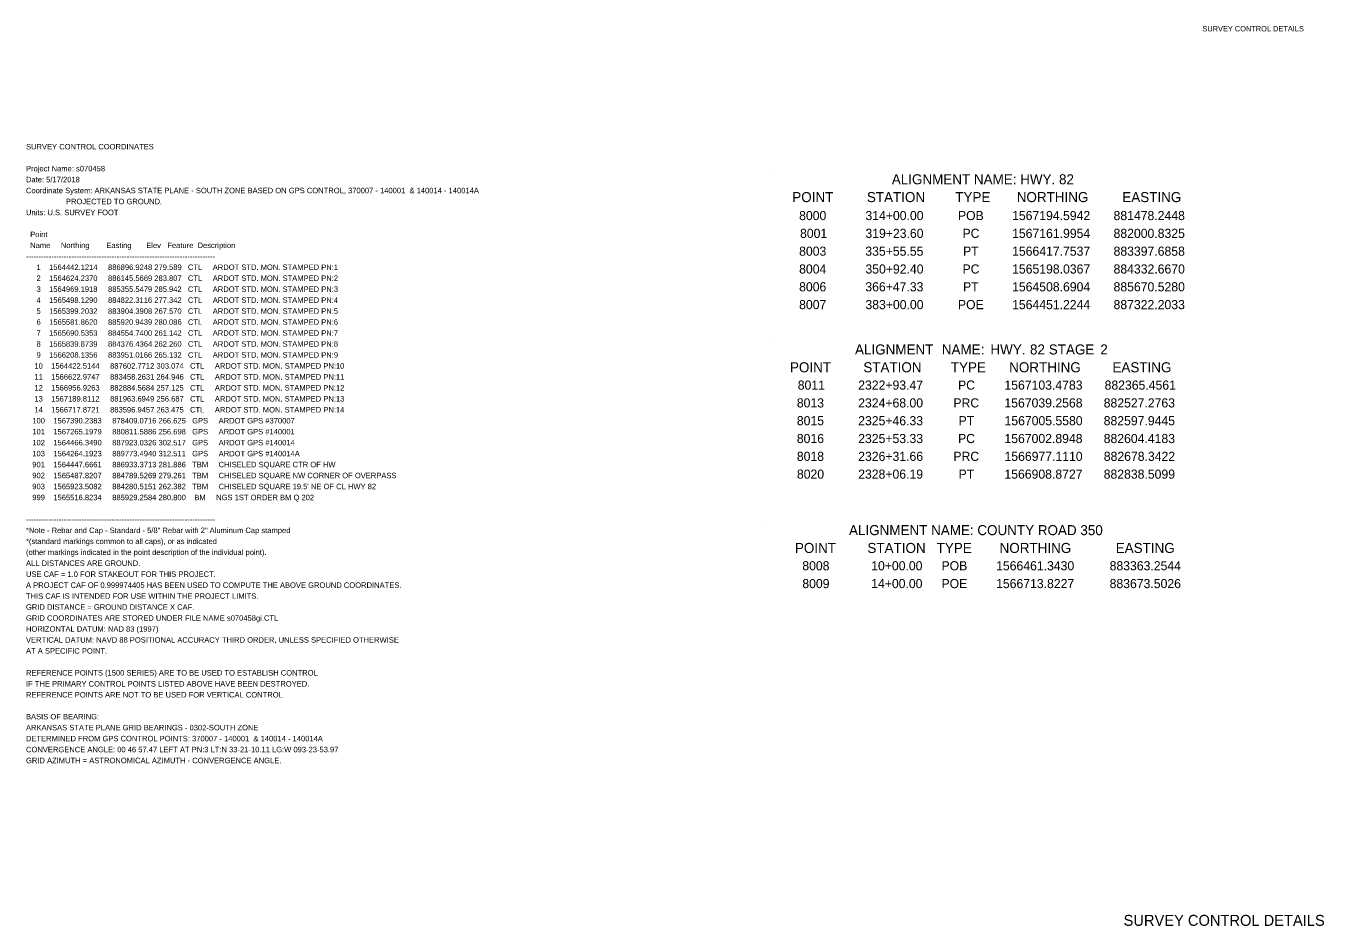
# Model space of a CAD drawing. Extents: x 878822 to 880243, y 1568127 to 1569112.
import ezdxf

# ---------------------------------------------------------------- set-up
doc = ezdxf.new("R2010")
doc.units = 0
for name, color, linetype in [('Default', 7, 'Continuous'), ('R_Border', 7, 'Continuous'), ('R_Border Prem', 7, 'Continuous')]:
    doc.layers.add(name, color=color, linetype=linetype)

msp = doc.modelspace()

# ---------------------------------------------------------------- linework, layer by layer
at = {"layer": 'R_Border Prem'}
for p, q in [((879640.9, 1568956), (879640.9, 1568956)), ((879642.8, 1568767.6), (879642.8, 1568767.6)), ((879629.3, 1568569.8), (879629.3, 1568569.8))]:
    msp.add_line(p, q, dxfattribs=at)

# ---------------------------------------------------------------- texts
at = {"layer": 'Default'}
for s, height, p in [('SURVEY CONTROL COORDINATES ', 6, (878822, 1568976.9)), ('Project Name: s070458 ', 6, (878822, 1568952.9)), ('Date: 5/17/2018 ', 6, (878822, 1568940.9)), ('ALIGNMENT NAME: HWY. 82', 11, (879770.1, 1568938.7)), ('Coordinate System: ARKANSAS STATE PLANE - SOUTH ZONE BASED ON GPS CONTROL, 370007 - 140001  & 140014 - 140014A', 6, (878822, 1568928.9)), ('                   PROJECTED TO GROUND. ', 6, (878822, 1568916.9)), ('POINT', 11, (879661.1, 1568919.2)), ('STATION', 11, (879742.8, 1568919.2)), ('TYPE', 11, (879839.6, 1568919.2)), ('NORTHING', 11, (879906.9, 1568919.2)), ('EASTING', 11, (880022.5, 1568919.2)), ('Units: U.S. SURVEY FOOT ', 6, (878822, 1568904.9)), ('8000', 10, (879668.6, 1568899.5)), ('314+00.00', 10, (879741.2, 1568899.5)), ('POB', 10, (879842.5, 1568899.5)), ('1567194.5942', 10, (879901.8, 1568899.5)), ('881478.2448', 10, (880012.9, 1568899.5)), ('  Point ', 6, (878822, 1568880.9)), ('8001', 10, (879669.6, 1568880)), ('319+23.60', 10, (879741.2, 1568880)), ('PC', 10, (879847.5, 1568880)), ('1567161.9954', 10, (879901.8, 1568880)), ('882000.8325', 10, (880012.9, 1568880)), ('  Name     Northing        Easting       Elev   Feature  Description ', 6, (878822, 1568868.9)), ('8003', 10, (879668.6, 1568860.5)), ('335+55.55', 10, (879741.1, 1568860.5)), ('PT', 10, (879848.1, 1568860.5)), ('1566417.7537', 10, (879901.8, 1568860.5)), ('883397.6858', 10, (880012.9, 1568860.5)), ('--------------------------------------------------------------------------- ', 6, (878822, 1568856.9)), ('8004', 10, (879668.6, 1568841)), ('350+92.40', 10, (879741.2, 1568841)), ('PC', 10, (879847.5, 1568841)), ('1565198.0367', 10, (879901.8, 1568841)), ('884332.6670', 10, (880012.9, 1568841)), ('     2    1564624.2370     886145.5669 283.807   CTL     ARDOT STD. MON. STAMPED PN:2 ', 6, (878822, 1568832.9)), ('     1    1564442.1214     886896.9248 279.589   CTL     ARDOT STD. MON. STAMPED PN:1 ', 6, (878822, 1568844.9)), ('     3    1564969.1918     885355.5479 285.942   CTL     ARDOT STD. MON. STAMPED PN:3 ', 6, (878822, 1568820.9)), ('8006', 10, (879668.6, 1568821.5)), ('366+47.33', 10, (879741.1, 1568821.5)), ('PT', 10, (879848.1, 1568821.5)), ('1564508.6904', 10, (879901.8, 1568821.5)), ('885670.5280', 10, (880012.9, 1568821.5)), ('     4    1565498.1290     884822.3116 277.342   CTL     ARDOT STD. MON. STAMPED PN:4 ', 6, (878822, 1568808.9)), ('8007', 10, (879668.6, 1568802)), ('383+00.00', 10, (879741.2, 1568802)), ('POE', 10, (879842.5, 1568802)), ('1564451.2244', 10, (879901.8, 1568802)), ('887322.2033', 10, (880012.9, 1568802)), ('     5    1565399.2032     883904.3908 267.570   CTL     ARDOT STD. MON. STAMPED PN:5 ', 6, (878822, 1568796.9)), ('     6    1565581.8620     885920.9439 280.086   CTL     ARDOT STD. MON. STAMPED PN:6 ', 6, (878822, 1568784.9)), ('     7    1565690.5353     884554.7400 261.142   CTL     ARDOT STD. MON. STAMPED PN:7 ', 6, (878822, 1568772.9)), ('     8    1565839.8739     884376.4364 262.260   CTL     ARDOT STD. MON. STAMPED PN:8 ', 6, (878822, 1568760.9)), ('     9    1566208.1356     883951.0166 265.132   CTL     ARDOT STD. MON. STAMPED PN:9 ', 6, (878822, 1568748.9)), ('ALIGNMENT', 11, (879729.8, 1568752.4)), (' NAME:', 11, (879820.8, 1568752.4)), (' HWY.', 11, (879874, 1568752.4)), (' 82', 11, (879917.3, 1568752.4)), (' STAGE', 11, (879937.9, 1568752.4)), (' 2', 11, (879994.3, 1568752.4)), ('    10    1564422.5144     887602.7712 303.074   CTL     ARDOT STD. MON. STAMPED PN:10 ', 6, (878822, 1568736.9)), ('POINT', 11, (879658.6, 1568732.9)), ('STATION', 11, (879738.9, 1568732.9)), ('TYPE', 11, (879834.7, 1568732.9)), ('NORTHING', 11, (879898.6, 1568732.9)), ('EASTING', 11, (880011.7, 1568732.9)), ('    11    1566622.9747     883458.2631 264.946   CTL     ARDOT STD. MON. STAMPED PN:11 ', 6, (878822, 1568724.9)), ('8011', 10, (879667.1, 1568713.9)), ('2322+93.47', 10, (879733.3, 1568713.9)), ('PC', 10, (879842.6, 1568713.9)), ('1567103.4783', 10, (879893.4, 1568713.9)), ('882365.4561', 10, (880003.1, 1568713.9)), ('    12    1566956.9263     882884.5684 257.125   CTL     ARDOT STD. MON. STAMPED PN:12 ', 6, (878822, 1568712.9)), ('    13    1567189.8112     881963.6949 256.687   CTL     ARDOT STD. MON. STAMPED PN:13 ', 6, (878822, 1568700.9)), ('    14    1566717.8721     883596.9457 263.475   CTL     ARDOT STD. MON. STAMPED PN:14 ', 6, (878822, 1568688.9)), ('8013', 10, (879666.1, 1568694.4)), ('2324+68.00', 10, (879733.3, 1568694.4)), ('PRC', 10, (879837.5, 1568694.4)), ('1567039.2568', 10, (879893.4, 1568694.4)), ('882527.2763', 10, (880002.1, 1568694.4)), ('   100    1567390.2383     878409.0716 266.625   GPS     ARDOT GPS #370007 ', 6, (878822, 1568676.9)), ('8015', 10, (879666.1, 1568674.9)), ('2325+46.33', 10, (879733.3, 1568674.9)), ('PT', 10, (879843.2, 1568674.9)), ('1567005.5580', 10, (879893.5, 1568674.9)), ('882597.9445', 10, (880002.1, 1568674.9)), ('   101    1567265.1979     880811.5886 256.698   GPS     ARDOT GPS #140001 ', 6, (878822, 1568664.9)), ('   102    1564466.3490     887923.0326 302.517   GPS     ARDOT GPS #140014 ', 6, (878822, 1568652.9)), ('8016', 10, (879666.1, 1568655.4)), ('2325+53.33', 10, (879733.3, 1568655.4)), ('PC', 10, (879842.6, 1568655.4)), ('1567002.8948', 10, (879893.4, 1568655.4)), ('882604.4183', 10, (880002.1, 1568655.4)), ('   103    1564264.1923     889773.4940 312.511   GPS     ARDOT GPS #140014A ', 6, (878822, 1568640.9)), ('8018', 10, (879666.1, 1568635.9)), ('2326+31.66', 10, (879733.3, 1568635.9)), ('PRC', 10, (879837.5, 1568635.9)), ('1566977.1110', 10, (879893.5, 1568635.9)), ('882678.3422', 10, (880002.2, 1568635.9)), ('   901    1564447.6661     886933.3713 281.886   TBM     CHISELED SQUARE CTR OF HW', 6, (878822, 1568628.9)), ('8020', 10, (879666.2, 1568616.4)), ('2328+06.19', 10, (879733.3, 1568616.4)), ('PT', 10, (879843.2, 1568616.4)), ('1566908.8727', 10, (879893.4, 1568616.4)), ('882838.5099', 10, (880002.1, 1568616.4)), ('   902    1565487.8207     884789.5269 279.261   TBM     CHISELED SQUARE NW CORNER OF OVERPASS ', 6, (878822, 1568616.9)), ("   903    1565923.5082     884280.5151 262.382   TBM     CHISELED SQUARE 19.5' NE OF CL HWY 82 ", 6, (878822, 1568604.9)), ('   999    1565516.8234     885929.2584 280.800    BM     NGS 1ST ORDER BM Q 202 ', 6, (878822, 1568592.9)), ('--------------------------------------------------------------------------- ', 6, (878822, 1568568.9)), ('*Note - Rebar and Cap - Standard - 5/8" Rebar with 2" Aluminum Cap stamped ', 6, (878822, 1568556.9)), ('ALIGNMENT NAME: COUNTY ROAD 350', 11, (879723.2, 1568554.6)), ('*(standard markings common to all caps), or as indicated ', 6, (878822, 1568544.9)), ('(other markings indicated in the point description of the individual point).  ', 6, (878822, 1568532.9)), ('POINT', 11, (879664, 1568535.1)), ('STATION', 11, (879743.4, 1568535.1)), ('TYPE', 11, (879819.2, 1568535.1)), ('NORTHING', 11, (879888.1, 1568535.1)), ('EASTING', 11, (880015.3, 1568535.1)), ('ALL DISTANCES ARE GROUND. ', 6, (878822, 1568520.9)), ('8008', 10, (879672.1, 1568516.1)), ('10+00.00', 10, (879747.5, 1568516.1)), ('POB', 10, (879824.5, 1568516.1)), ('1566461.3430', 10, (879884.3, 1568516.1)), ('883363.2544', 10, (880008.6, 1568516.1)), ('USE CAF = 1.0 FOR STAKEOUT FOR THIS PROJECT. ', 6, (878822, 1568508.9)), ('A PROJECT CAF OF 0.999974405 HAS BEEN USED TO COMPUTE THE ABOVE GROUND COORDINATES. ', 6, (878822, 1568496.9)), ('8009', 10, (879672.1, 1568496.6)), ('14+00.00', 10, (879747.5, 1568496.6)), ('POE', 10, (879824.5, 1568496.6)), ('1566713.8227', 10, (879884.3, 1568496.6)), ('883673.5026', 10, (880008.6, 1568496.6)), ('THIS CAF IS INTENDED FOR USE WITHIN THE PROJECT LIMITS. ', 6, (878822, 1568484.9)), ('GRID DISTANCE = GROUND DISTANCE X CAF. ', 6, (878822, 1568472.9)), ('GRID COORDINATES ARE STORED UNDER FILE NAME s070458gi.CTL  ', 6, (878822, 1568460.9)), ('HORIZONTAL DATUM: NAD 83 (1997) ', 6, (878822, 1568448.9)), ('VERTICAL DATUM: NAVD 88 POSITIONAL ACCURACY THIRD ORDER, UNLESS SPECIFIED OTHERWISE  ', 6, (878822, 1568436.9)), ('AT A SPECIFIC POINT. ', 6, (878822, 1568424.9)), ('REFERENCE POINTS (1500 SERIES) ARE TO BE USED TO ESTABLISH CONTROL ', 6, (878822, 1568400.9)), ('REFERENCE POINTS ARE NOT TO BE USED FOR VERTICAL CONTROL ', 6, (878822, 1568376.9)), ('IF THE PRIMARY CONTROL POINTS LISTED ABOVE HAVE BEEN DESTROYED. ', 6, (878822, 1568388.9)), ('BASIS OF BEARING: ', 6, (878822, 1568352.9)), ('ARKANSAS STATE PLANE GRID BEARINGS - 0302-SOUTH ZONE ', 6, (878822, 1568340.9)), ('DETERMINED FROM GPS CONTROL POINTS: 370007 - 140001  & 140014 - 140014A', 6, (878822, 1568328.9)), ('CONVERGENCE ANGLE: 00 46 57.47 LEFT AT PN:3 LT:N 33-21-10.11 LG:W 093-23-53.97', 6, (878822, 1568316.9)), ('GRID AZIMUTH = ASTRONOMICAL AZIMUTH - CONVERGENCE ANGLE.', 6, (878822, 1568304.9))]:
    msp.add_text(s, height=height, dxfattribs=at).set_placement(p)
at = {"layer": 'R_Border'}
msp.add_text('SURVEY CONTROL DETAILS', height=12, rotation=360, dxfattribs=at).set_placement((880023.9, 1568126.9))
at = {"layer": 'R_Border Prem'}
msp.add_text('SURVEY CONTROL DETAILS', height=5.862, dxfattribs=at).set_placement((880110.2, 1569106.1))

doc.saveas('drawing.dxf')
